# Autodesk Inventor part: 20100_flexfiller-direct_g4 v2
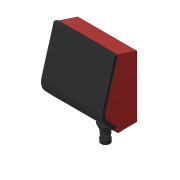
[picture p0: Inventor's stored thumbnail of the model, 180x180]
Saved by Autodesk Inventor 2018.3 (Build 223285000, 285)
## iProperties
Created: 2021-11
Part Number: 20100_flexfiller-direct_g4 v2
Material: Generic
Document SubType Name: Modeling
Designer: kasius
Density: 1 g/cm^3
Appearance: Default
RuleStatus: InUse
Author: kasius
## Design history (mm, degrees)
revolve "Revolution1" stored, may be unused: angle "d1" = 90 deg
sketch "Sketch1"
  geometry: L1 (0, 0)-(0, -12.085); L2 (15.769, 0.009)-(15.76, 0); L3 (15.76, 0)-(11.094, 0); L4 (41.402, 16.381)-(30.086, 15.39); L5 (30.086, 15.39)-(30.086, 13.095); L6 (26.286, 13.095)-(26.286, 15.058); L7 (30.086, 13.095)-(26.286, 13.095); L8 (73.645, 10)-(73.645, 21.824); L9 (102.953, 0)-(96.935, 0); L10 (68.892, 22.942)-(62.475, 25.027); L11 (60.645, 18.723)-(73.645, 18.496); L12 (69.03, 22.698)-(68.892, 22.942); L13 (69.291, 22.889)-(69.03, 22.698); L14 (95.645, 4.882)-(95.645, 0); L15 (73.645, 18.496)-(99.645, 10.267); L16 (102.564, 12.359)-(69.291, 22.889); L17 (99.645, 10.267)-(99.645, 6.263); L18 (99.645, 6.263)-(95.645, 4.882); L19 (95.645, 0)-(102.564, 0); L20 (19.82, 13.926)-(19.486, 13.926); L21 (19.486, 13.926)-(19.486, 14.495); L22 (19.486, 14.495)-(15.486, 14.495); L23 (15.486, 14.495)-(15.486, 14.14); L24 (11.986, 14.895)-(12.986, 15.896); L25 (15.486, 14.14)-(11.986, 14.14); L26 (11.986, 14.14)-(11.986, 14.895); L27 (60.645, 0)-(60.645, 18.723); L28 (23.286, 14.795)-(23.286, 14.495); L29 (12.986, 15.896)-(12.986, 16.496); L30 (12.986, 16.496)-(0.486, 16.272); L31 (0.486, 16.272)-(0, 15.769); L32 (17.5, 11.094)-(17.5, 0); L33 (0, 11.094)-(17.5, 11.094); L34 (-0.003, 15.766)-(0, 15.769); L35 (0, 15.769)-(0, 11.094); L36 (73.645, 21.824)-(104.607, 21.824); L37 (104.607, 21.824)-(104.607, 10); L38 (104.607, 10)-(73.645, 10); L39 (62.475, 25.027)-(41.402, 16.381); L40 (17.5, 0)-(60.645, 0); L41 (96.935, 0)-(96.935, -16.601); L42 (96.935, -16.601)-(102.953, -16.601); L43 (115.165, -62.966)-(97.999, -46.389); L44 (97.388, -44.95)-(97.388, -29.388); L45 (97.388, -29.388)-(98.288, -27.901); L46 (98.288, -27.901)-(98.288, 23.9); L47 (122.833, -53.405)-(113.8, -62.758); L48 (358.727, -62.017)-(354.807, -48.785); L49 (287.205, -82.526)-(358.727, -62.017); L50 (102.953, -16.601)-(102.953, 0); L51 (102.564, 0)-(102.564, 12.359); L52 (287.263, -82.721)-(287.205, -82.526); L53 (353.477, -48.546)-(351.411, -52.274); L54 (286.848, -83.092)-(287.263, -82.721); L55 (330.391, 24.518)-(353.629, -46.958); L56 (354.807, -48.785)-(194.454, -94.766); L57 (351.411, -52.274)-(171.256, -103.932); L58 (198.749, -108.354)-(286.848, -83.092); L59 (157.583, -85.573)-(124.247, -53.38); L60 (171.256, -103.932)-(115.165, -62.966); L61 (100.288, 25.9)-(328.489, 25.9); L62 (113.811, -63.116)-(147.424, -95.557); L63 (23.286, 14.495)-(22.968, 14.466); L64 (26.286, 15.058)-(23.286, 14.795); A1 r 2 centre (100.288, 23.9) between (100.288, 25.9) and (98.288, 23.9); A2 r 2 centre (99.388, -44.95) between (97.388, -44.95) and (97.999, -46.389); A3 r 1 centre (123.552, -54.1) between (124.247, -53.38) and (122.833, -53.405); A4 r 0.25 centre (113.98, -62.932) between (113.8, -62.758) and (113.811, -63.116); A5 r 2 centre (351.727, -47.577) between (353.477, -48.546) and (353.629, -46.958); A6 r 38 centre (183.98, -58.238) between (157.583, -85.573) and (194.454, -94.766); A7 r 52.896 centre (184.169, -57.507) between (147.424, -95.557) and (198.749, -108.354); A8 r 1.765 centre (21.521, 13.455) between (22.968, 14.466) and (19.82, 13.926); A9 r 2 centre (328.489, 23.9) between (330.391, 24.518) and (328.489, 25.9); 1 further point
  constraints: 128 end point, 18 point on circle, 9 centre point, 3 point on line, 2 tangent
extrude "Extrusion1" cut sketch "Sketch1" extent not by distance; stored distance "d2" = 30; taper "d3" = 0 deg
pattern_circular "Circular Pattern1" dims angle "d5" = 360 deg
extrude "Extrusion2" new body sketch "Sketch1" distance "d7" = 129; taper "d9" = 0 deg; dims "d8" = 93, "d10" = 0
revolve "Revolution2" stored, may be unused: angle "d11" = 90 deg
extrude "Extrusion3" new body sketch "Sketch1" distance "d12" = 132; taper "d14" = 0 deg; dims "d13" = 96, "d15" = 0
sketch "Sketch2"
  geometry: L1 (-87.904, 99.188)-(-87.904, 97.188); L2 (-87.904, 97.188)-(-90.106, 94.988); L3 (-90.106, 94.988)-(-90.106, 85.467); L4 (-90.106, 85.467)-(-89.069, 84.389); L5 (-89.069, 84.389)-(-89.069, 75.974); L6 (-89.069, 75.974)-(-90.406, 74.638); L7 (-111.338, -99.469)-(-111.338, -111.554); L8 (-90.99, 74.638)-(-91.857, 76.138); L9 (34.055, 101.488)-(34.055, 91.766); L10 (-90.406, 74.638)-(-90.99, 74.638); L11 (54.555, 101.488)-(54.555, 91.766); L12 (75.055, 101.488)-(75.055, 91.766); L13 (28.805, 103.36)-(34.055, 103.36); L14 (34.055, 103.36)-(34.055, 96.627); L15 (34.055, 96.627)-(28.805, 96.627); L16 (28.805, 96.627)-(28.805, 103.36); L17 (49.305, 103.36)-(54.555, 103.36); L18 (54.555, 103.36)-(54.555, 96.627); L19 (54.555, 96.627)-(49.305, 96.627); L20 (49.305, 96.627)-(49.305, 103.36); L21 (69.805, 103.36)-(75.055, 103.36); L22 (75.055, 103.36)-(75.055, 96.627); L23 (75.055, 96.627)-(69.805, 96.627); L24 (69.805, 96.627)-(69.805, 103.36); L25 (-46.393, 74.638)-(-46.393, 95.651); L26 (-99.398, 74.638)-(-99.398, 95.651); L27 (-91.857, 76.138)-(-91.857, 98.038); L28 (-91.857, 98.038)-(-99.398, 98.038); L29 (-99.398, 98.038)-(-99.398, 103.293); L30 (-99.398, 103.293)-(-86.351, 103.293); L31 (-86.351, 103.293)-(-86.351, 99.188); L32 (-86.351, 99.188)-(-87.904, 99.188); L33 (-37.101, 94.988)-(-34.9, 97.188); L34 (-34.9, 97.188)-(-34.9, 99.188); L35 (-34.9, 99.188)-(-33.347, 99.188); L36 (-33.347, 99.188)-(-33.347, 103.293); L37 (-33.347, 103.293)-(-46.393, 103.293); L38 (-46.393, 103.293)-(-46.393, 98.038); L39 (-46.393, 98.038)-(-38.853, 98.038); L40 (-38.853, 98.038)-(-38.853, 76.138); L41 (-38.853, 76.138)-(-37.986, 74.638); L42 (-37.401, 74.638)-(-36.065, 75.974); L43 (-36.065, 75.974)-(-36.065, 84.389); L44 (-36.065, 84.389)-(-37.101, 85.467); L45 (-37.101, 85.467)-(-37.101, 94.988); L46 (40.955, 97.488)-(40.955, 97.988); L47 (40.955, 97.988)-(39.305, 97.988); L48 (39.305, 97.988)-(39.305, 99.488); L49 (39.305, 99.488)-(40.955, 99.488); L50 (40.955, 99.488)-(40.955, 99.988); L51 (39.455, 101.488)-(37.206, 101.488); L52 (37.206, 101.488)-(37.206, 95.988); L53 (37.206, 95.988)-(39.455, 95.988); L54 (61.455, 97.488)-(61.455, 97.988); L55 (61.455, 97.988)-(59.805, 97.988); L56 (59.805, 97.988)-(59.805, 99.488); L57 (59.805, 99.488)-(61.455, 99.488); L58 (61.455, 99.488)-(61.455, 99.988); L59 (81.955, 97.988)-(80.305, 97.988); L60 (80.305, 97.988)-(80.305, 99.488); L61 (80.305, 99.488)-(81.955, 99.488); L62 (81.955, 99.488)-(81.955, 99.988); L63 (-37.986, 74.638)-(-37.401, 74.638); L64 (78.206, 101.488)-(78.206, 95.988)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; A1 r 1.5 centre (39.455, 99.988) between (40.955, 99.988) and (39.455, 101.488); A2 r 1.5 centre (39.455, 97.488) between (39.455, 95.988) and (40.955, 97.488); A3 r 1.5 centre (59.955, 97.488) between (59.955, 95.988) and (61.455, 97.488); A4 r 1.5 centre (80.455, 99.988) between (81.955, 99.988) and (80.455, 101.488); A5 r 1.5 centre (80.455, 97.488) between (80.455, 95.988) and (81.955, 97.488); A6 r 1.5 centre (59.955, 99.988) between (61.455, 99.988) and (59.955, 101.488); 1 further point
  constraints: 150 end point, 12 point on circle, 6 centre point, 3 midpoint, 3 point on line, 2 parallel, 1 horizontal, 1 perpendicular, 1 vertical
  dimensions: "d16" = 25 distance of L7.start L71.end
revolve "Revolution3" stored, may be unused: angle "d17" = 90 deg
revolve "Revolution5" stored, may be unused: angle "d22" = 90 deg
revolve "Revolution4" stored, may be unused: angle "d18" = 90 deg
pattern_linear "Rectangular Pattern1" dims "d21" = 53.005
revolve "Revolution6" stored, may be unused: angle "d23" = 90 deg
pattern_linear "Rectangular Pattern2" dims "d26" = 20.5
sketch "Sketch3"
  geometry: L1 (222, -2)-(0, -2); L2 (93, -100.288)-(93, -2); L3 (111.295, 228.201)-(111.295, 187.667); L4 (93, -2)-(93, 40.614); L5 (111.295, 180.2)-(116.295, 171.54); L6 (116.295, 171.54)-(106.295, 171.54); L7 (106.295, 171.54)-(111.295, 180.2); L8 (190.635, 85.29)-(199.295, 80.29); L9 (199.295, 80.29)-(190.635, 75.29); L10 (190.635, 75.29)-(190.635, 85.29); L11 (99.171, 75.29)-(99.171, 85.29); L12 (90.51, 80.29)-(99.171, 75.29); L13 (99.171, 85.29)-(90.51, 80.29); L14 (116.295, 55.703)-(106.295, 55.703); L15 (111.295, 47.043)-(116.295, 55.703); L16 (106.295, 55.703)-(111.295, 47.043); L17 (188.795, 171.2)-(172.795, 171.2); L18 (172.795, 178.2)-(188.795, 178.2); L19 (63.316, 155.2)-(50.316, 155.2); L20 (50.316, 162.2)-(63.316, 162.2); L21 (63.316, 171.2)-(50.316, 171.2); L22 (50.316, 178.2)-(63.316, 178.2); L23 (176.295, 161.2)-(176.295, 148.2); L24 (169.295, 148.2)-(169.295, 161.2); L25 (154.311, 13.3)-(154.311, 29.3); L26 (161.311, 29.3)-(161.311, 13.3); L27 (184.311, 9.8)-(171.311, 9.8); L28 (171.311, 16.8)-(184.311, 16.8); L29 (184.311, 25.8)-(171.311, 25.8); L30 (171.311, 32.8)-(184.311, 32.8); L31 (80.316, 174.7)-(80.316, 158.7); L32 (73.316, 158.7)-(73.316, 174.7); L33 (192.295, 161.2)-(192.295, 148.2); L34 (185.295, 148.2)-(185.295, 161.2); L35 (21.295, 173.058)-(21.295, 187.667); L36 (21.295, 187.667)-(201.295, 187.667); L37 (201.295, 187.667)-(201.295, 181.2); L38 (201.295, 181.2)-(202.295, 181.2); L39 (160.395, -3.2)-(160.395, -0.2); L40 (206.762, 181.2)-(206.762, -0.2); L41 (206.762, -0.2)-(180.395, -0.2); L42 (180.395, -0.2)-(180.395, -3.2); L43 (180.395, -3.2)-(160.395, -3.2); L44 (160.395, -0.2)-(134.984, -0.2); L45 (134.984, -0.2)-(21.295, 173.058); L46 (202.295, 181.2)-(206.762, 181.2); L47 (160.395, -1.089)-(180.395, -1.089); A1 r 3.5 centre (171.311, 13.3) between (171.311, 16.8) and (171.311, 9.8); A2 r 3.5 centre (171.311, 29.3) between (171.311, 32.8) and (171.311, 25.8); A3 r 3.5 centre (188.795, 174.7) between (188.795, 171.2) and (188.795, 178.2); A4 r 3.5 centre (63.316, 158.7) between (63.316, 155.2) and (63.316, 162.2); A5 r 3.5 centre (63.316, 174.7) between (63.316, 171.2) and (63.316, 178.2); A6 r 3.5 centre (172.795, 161.2) between (176.295, 161.2) and (169.295, 161.2); A7 r 3.5 centre (172.795, 148.2) between (169.295, 148.2) and (176.295, 148.2); A8 r 3.5 centre (157.811, 13.3) between (154.311, 13.3) and (161.311, 13.3); A9 r 3.5 centre (157.811, 29.3) between (161.311, 29.3) and (154.311, 29.3); A10 r 3.5 centre (184.311, 13.3) between (184.311, 9.8) and (184.311, 16.8); A11 r 3.5 centre (184.311, 29.3) between (184.311, 25.8) and (184.311, 32.8); A12 r 3.5 centre (76.816, 174.7) between (80.316, 174.7) and (73.316, 174.7); A13 r 3.5 centre (76.816, 158.7) between (73.316, 158.7) and (80.316, 158.7); A14 r 3.5 centre (188.795, 161.2) between (192.295, 161.2) and (185.295, 161.2); A15 r 3.5 centre (188.795, 148.2) between (185.295, 148.2) and (192.295, 148.2); A16 r 3.5 centre (172.795, 174.7) between (172.795, 178.2) and (172.795, 171.2); A17 r 3.5 centre (50.316, 158.7) between (50.316, 162.2) and (50.316, 155.2); A18 r 3.5 centre (50.316, 174.7) between (50.316, 178.2) and (50.316, 171.2); 1 further point
  constraints: 94 end point, 36 point on circle, 18 centre point, 3 point on line, 1 midpoint, 1 perpendicular, 1 vertical, 1 other
extrude "Extrusion4" new body sketch "Sketch3" distance "d27" = 4; taper "d28" = 0 deg
extrude "Extrusion5" join sketch "Sketch3" distance "d29" = 3.5; taper "d30" = 0 deg
extrude "Extrusion6" join sketch "Sketch3" distance "d31" = 20; taper "d32" = 0 deg
chamfer "Chamfer1" distance "d33" = 2; stored, may be unused: second distance "d34" = 2, angle "d35" = 45 deg
body "Solid1"
body "Solid2"
body "Solid3"
body "Solid4"
body "Solid5"
body "Solid6"
